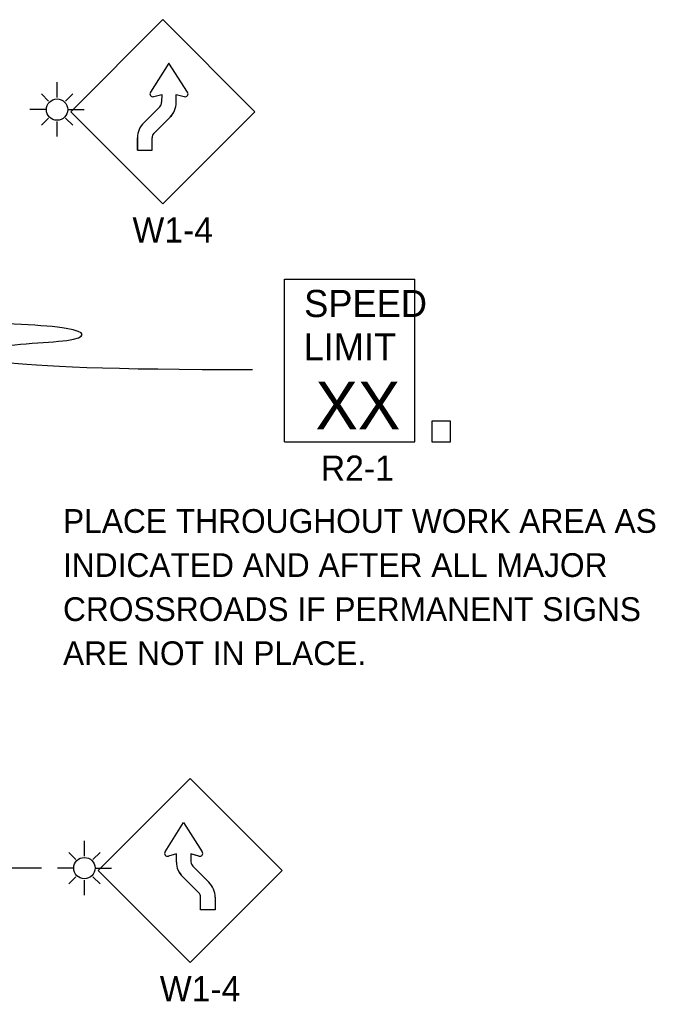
# Model space of a CAD drawing. Extents: x 16748 to 18475, y 7008 to 8262.
# Drawn here: x 17236.5 to 17424.2, y 7635.3 to 7924.9 of the extents above; entities that cross this region are included whole.
import ezdxf

# ---------------------------------------------------------------- set-up
doc = ezdxf.new("R2010")
doc.units = 0
doc.layers.add('TRAFFIC_SIGNS_PR', color=7, linetype='Continuous')
doc.layers.add('TYPICAL_TEXT_DIMEN_PR', color=7, linetype='Continuous')

msp = doc.modelspace()

# ---------------------------------------------------------------- linework, layer by layer
at = {"layer": 'TRAFFIC_SIGNS_PR'}
for p, q in [((17278.82, 7924.87), (17251.66, 7897.72)), ((17305.97, 7897.72), (17278.82, 7924.87)), ((17247.56, 7901.89), (17247.56, 7906.39)), ((17245.04, 7900.85), (17242.94, 7902.96)), ((17250.07, 7900.85), (17252.18, 7902.96)), ((17244.4, 7898.34), (17239.57, 7898.34)), ((17250.71, 7898.34), (17255.59, 7898.34)), ((17251.66, 7897.72), (17278.82, 7870.57)), ((17273.16, 7894.47), (17277.87, 7899.18)), ((17277.87, 7899.18), (17273.16, 7894.47)), ((17278.82, 7870.57), (17305.97, 7897.72)), ((17245.04, 7895.82), (17242.94, 7893.71)), ((17247.56, 7890.37), (17247.56, 7894.78)), ((17250.07, 7895.82), (17252.18, 7893.72)), ((17276.21, 7891.42), (17280.93, 7896.13)), ((17276.21, 7891.41), (17280.93, 7896.13)), ((17271.29, 7886.35), (17271.29, 7890.05)), ((17275.61, 7886.35), (17275.61, 7890.05)), ((17271.29, 7886.35), (17275.61, 7886.35)), ((17314.72, 7848.3), (17353.12, 7848.3)), ((17314.72, 7800.3), (17314.72, 7848.3)), ((17353.12, 7800.3), (17353.12, 7848.3)), ((17314.72, 7800.3), (17353.12, 7800.3)), ((17259.74, 7673.9), (17286.89, 7701.06)), ((17314.05, 7673.9), (17286.89, 7701.06)), ((17255.64, 7678.16), (17255.64, 7682.66)), ((17253.12, 7677.12), (17251.02, 7679.23)), ((17258.15, 7677.12), (17260.26, 7679.23)), ((17252.48, 7674.61), (17247.65, 7674.61)), ((17258.79, 7674.61), (17263.67, 7674.61)), ((17286.89, 7646.75), (17259.74, 7673.9)), ((17314.05, 7673.9), (17286.89, 7646.75)), ((17292.37, 7670.44), (17287.65, 7675.15)), ((17287.65, 7675.15), (17292.37, 7670.44)), ((17253.12, 7672.09), (17251.02, 7669.99)), ((17255.64, 7666.64), (17255.64, 7671.05)), ((17258.15, 7672.09), (17260.26, 7669.99)), ((17289.31, 7667.39), (17284.6, 7672.1)), ((17289.31, 7667.38), (17284.6, 7672.1))]:
    msp.add_line(p, q, dxfattribs=at)
for points in [[(17286.08, 7903.46), (17280.6, 7912.07), (17275.12, 7903.46)], [(17286.08, 7903.46), (17280.6, 7912.07), (17275.12, 7903.46)], [(17276.08, 7902.16), (17278.44, 7902.81), (17278.43, 7900.51)], [(17276.08, 7902.16), (17276.91, 7902.39), (17278.44, 7902.81), (17278.43, 7900.51)], [(17282.75, 7900.44), (17282.75, 7902.81), (17285.12, 7902.16)], [(17271.29, 7890.05), (17271.29, 7886.35), (17275.61, 7886.35), (17275.61, 7890.05)], [(17279.44, 7679.43), (17284.93, 7688.04), (17290.41, 7679.43)], [(17279.45, 7679.43), (17284.93, 7688.04), (17290.41, 7679.43)], [(17282.78, 7676.41), (17282.77, 7678.78), (17280.41, 7678.13)], [(17282.78, 7676.41), (17282.77, 7678.78), (17280.41, 7678.13)], [(17289.45, 7678.13), (17287.09, 7678.78), (17287.09, 7676.48)], [(17289.45, 7678.13), (17288.61, 7678.36), (17287.09, 7678.78), (17287.09, 7676.48)], [(17294.23, 7666.02), (17294.23, 7662.32), (17289.92, 7662.32), (17289.92, 7666.02)]]:
    msp.add_lwpolyline(points, dxfattribs=at)
msp.add_lwpolyline([(17358.14, 7800.3), (17363.73, 7800.3), (17363.73, 7806.47), (17358.14, 7806.47)], close=True, dxfattribs=at)
for centre in [(17247.56, 7898.33), (17255.64, 7674.61)]:
    msp.add_circle(centre, 3.15, dxfattribs=at)
for centre, radius, start, end in [((17275.85, 7902.99), 0.864, 147.5204, 285.3986), ((17275.85, 7902.99), 0.866, 147.5288, 285.3852), ((17285.35, 7902.99), 0.866, 254.6799, 32.2804), ((17276.58, 7900.51), 1.85, 314.2125, 0), ((17276.58, 7900.51), 1.85, 314.2123, 0.1238), ((17276.58, 7900.51), 6.17, 314.2125, 359.3819), ((17276.58, 7900.51), 6.17, 314.7687, 359.3755), ((17277.46, 7890.05), 6.17, 134.2125, 180), ((17277.46, 7890.05), 6.17, 134.2125, 180), ((17277.46, 7890.05), 6.17, 134.2117, 180), ((17277.46, 7890.05), 1.85, 132.372, 180), ((17277.46, 7890.05), 1.85, 134.2125, 180), ((17280.18, 7678.96), 0.866, 147.7292, 285.3172), ((17280.18, 7678.96), 0.866, 147.7196, 285.3201), ((17270.34, 7685.22), 10.8, 327.5335, 327.5431), ((17289.68, 7678.96), 0.866, 254.6148, 32.4712), ((17283.26, 7667.71), 10.8, 105.3192, 105.32), ((17288.94, 7676.48), 6.17, 180.6181, 225.7875), ((17288.94, 7676.48), 6.17, 180.6245, 225.2313), ((17288.94, 7676.48), 1.85, 180, 225.7875), ((17288.94, 7676.48), 1.85, 179.8762, 225.7877), ((17288.06, 7666.02), 6.17, 0, 45.7883), ((17288.06, 7666.02), 1.85, 0, 47.628)]:
    msp.add_arc(centre, radius, start, end, dxfattribs=at)
at = {"layer": 'TYPICAL_TEXT_DIMEN_PR'}
msp.add_line((17242.95, 7674.61), (17192.54, 7674.61), dxfattribs=at)
msp.add_open_spline([(17305.29, 7821.56), (17220.51, 7821.56), (17220.51, 7829.44), (17256.47, 7829.44), (17256.47, 7834.43), (17231.65, 7835.26), (17218.73, 7835.41)], degree=3, dxfattribs=at)

# ---------------------------------------------------------------- texts
at = {"layer": 'TRAFFIC_SIGNS_PR'}
for s, height, p in [('W1-4', 7.44, (17269.82, 7859.13)), ('SPEED', 8, (17320.49, 7837.16)), ('LIMIT', 8, (17320.33, 7824.36)), ('XX', 14.031, (17323.84, 7804.06)), ('R2-1', 7.44, (17325.4, 7788.86)), ('PLACE THROUGHOUT WORK AREA AS', 7, (17249.32, 7773.5)), ('INDICATED AND AFTER ALL MAJOR', 7, (17249.32, 7760.5)), ('CROSSROADS IF PERMANENT SIGNS', 7, (17249.32, 7747.5)), ('ARE NOT IN PLACE.', 7, (17249.32, 7734.5)), ('W1-4', 7.44, (17277.9, 7635.31))]:
    msp.add_text(s, height=height, dxfattribs=at).set_placement(p)

doc.saveas('drawing.dxf')
